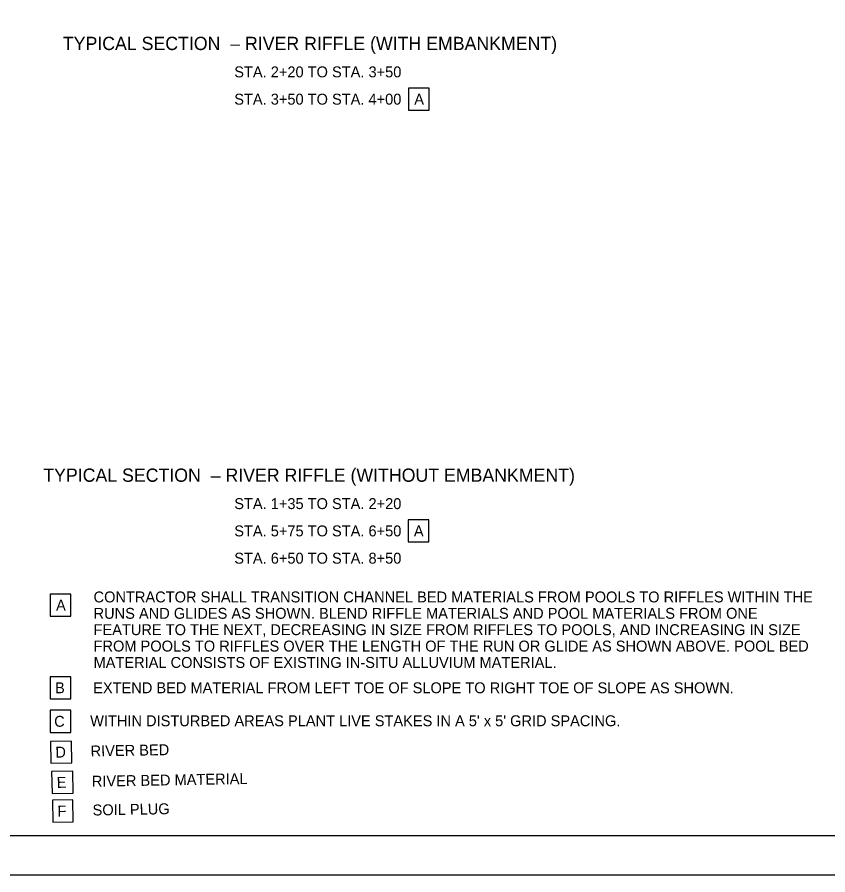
# Model space of a CAD drawing. Extents: x 0 to 34, y 0 to 22.
# Drawn here: x 13.9 to 24.3, y 0 to 11 of the extents above; entities that cross this region are included whole.
import ezdxf

# ---------------------------------------------------------------- set-up
doc = ezdxf.new("R2010")
doc.units = 0
for name, color, linetype in [('CS-ALGN-CNTR', 7, 'Continuous'), ('CS-ALGN-TEXT', 7, 'Continuous'), ('CS-ANNO-TABL', 7, 'Continuous')]:
    doc.layers.add(name, color=color, linetype=linetype)

msp = doc.modelspace()

# ---------------------------------------------------------------- linework, layer by layer
at = {"layer": 'CS-ALGN-CNTR'}
msp.add_lwpolyline([(0, 0), (34, 0), (34, 22), (0, 22)], close=True, dxfattribs=at)
at = {"layer": 'CS-ALGN-TEXT'}
msp.add_lwpolyline([(1.5, 21.5), (33.5, 21.5), (33.5, 0.5), (1.5, 0.5)], close=True, dxfattribs=at)
at = {"layer": 'CS-ANNO-TABL'}
for points in [[(18.916, 9.808), (19.181, 9.808), (19.181, 10.088), (18.916, 10.088)], [(18.911, 4.271), (19.175, 4.271), (19.175, 4.551), (18.911, 4.551)], [(14.321, 3.319), (14.586, 3.319), (14.586, 3.599), (14.321, 3.599)], [(14.321, 2.259), (14.583, 2.259), (14.583, 2.539), (14.321, 2.539)], [(14.319, 1.827), (14.584, 1.827), (14.584, 2.111), (14.319, 2.111)], [(14.327, 1.432), (14.598, 1.436), (14.593, 1.716), (14.322, 1.712)], [(14.343, 1.044), (14.614, 1.049), (14.609, 1.329), (14.338, 1.324)], [(14.353, 0.676), (14.613, 0.68), (14.609, 0.96), (14.348, 0.956)]]:
    msp.add_lwpolyline(points, close=True, dxfattribs=at)

# ---------------------------------------------------------------- texts
for s, height, p in [('TYPICAL SECTION  ‒ RIVER RIFFLE (WITH EMBANKMENT)', 0.17, (14.482, 10.578)), ('STA. 2+20 TO STA. 3+50', 0.14, (16.681, 10.228)), ('STA. 3+50 TO STA. 4+00', 0.14, (16.681, 9.878)), ('A', 0.14, (18.99, 9.878)), ('TYPICAL SECTION  ‒ RIVER RIFFLE (WITHOUT EMBANKMENT)', 0.17, (14.231, 5.041)), ('STA. 1+35 TO STA. 2+20', 0.14, (16.681, 4.691)), ('STA. 5+75 TO STA. 6+50', 0.14, (16.681, 4.341)), ('A', 0.14, (18.985, 4.341)), ('STA. 6+50 TO STA. 8+50', 0.14, (16.681, 3.991)), ('CONTRACTOR SHALL TRANSITION CHANNEL BED MATERIALS FROM POOLS TO RIFFLES WITHIN THE ', 0.14, (14.876, 3.494)), ('A', 0.14, (14.395, 3.389)), ('RUNS AND GLIDES AS SHOWN. BLEND RIFFLE MATERIALS AND POOL MATERIALS FROM ONE ', 0.14, (14.876, 3.284)), ('FEATURE TO THE NEXT, DECREASING IN SIZE FROM RIFFLES TO POOLS, AND INCREASING IN SIZE ', 0.14, (14.876, 3.074)), ('FROM POOLS TO RIFFLES OVER THE LENGTH OF THE RUN OR GLIDE AS SHOWN ABOVE. POOL BED ', 0.14, (14.876, 2.864)), ('MATERIAL CONSISTS OF EXISTING IN-SITU ALLUVIUM MATERIAL.', 0.14, (14.876, 2.654)), ('B', 0.14, (14.382, 2.329)), ('EXTEND BED MATERIAL FROM LEFT TOE OF SLOPE TO RIGHT TOE OF SLOPE AS SHOWN.', 0.14, (14.871, 2.329)), ('C', 0.14, (14.371, 1.899)), ("WITHIN DISTURBED AREAS PLANT LIVE STAKES IN A 5' x 5' GRID SPACING.", 0.14, (14.832, 1.906))]:
    msp.add_text(s, height=height, dxfattribs=at).set_placement(p)
for s, p in [('RIVER BED', (14.839, 1.518)), ('D', (14.387, 1.503)), ('E', (14.404, 1.115)), ('RIVER BED MATERIAL', (14.855, 1.13)), ('F', (14.413, 0.747)), ('SOIL PLUG', (14.865, 0.761))]:
    msp.add_text(s, height=0.14, rotation=1, dxfattribs=at).set_placement(p)

doc.saveas('drawing.dxf')
